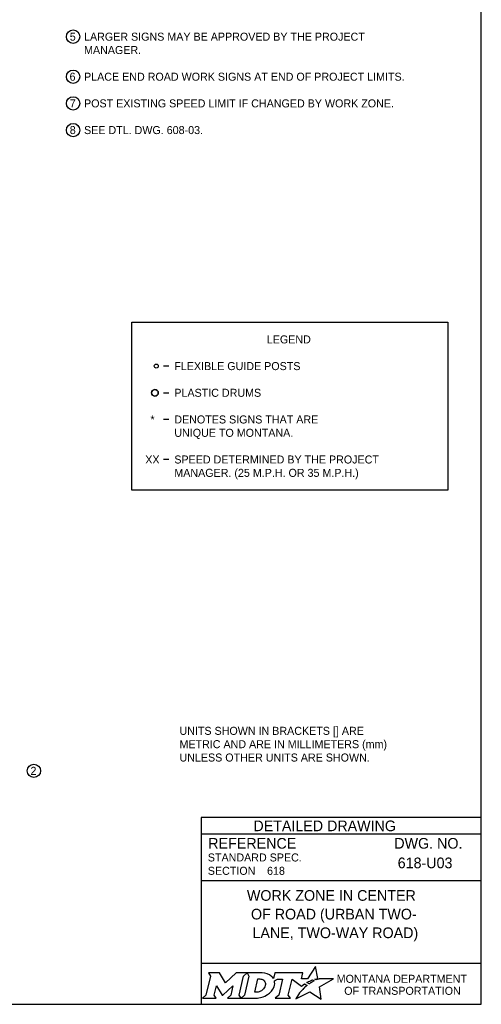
# Model space of a CAD drawing. Extents: x 49991.4 to 50021, y 49987.6 to 50011.4.
# Drawn here: x 50005.15 to 50008.61, y 50000.06 to 50007.44 of the extents above; entities that cross this region are included whole.
import ezdxf

# ---------------------------------------------------------------- set-up
doc = ezdxf.new("R2010")
doc.units = 0
doc.layers.add('Level 1', color=7, linetype='Continuous')
doc.layers.add('Level 2', color=7, linetype='Continuous')

msp = doc.modelspace()

# ---------------------------------------------------------------- linework, layer by layer
at = {"layer": 'Level 1'}
msp.add_lwpolyline([(50008.6146, 50011.2628), (50000.3356, 50011.2628), (50000.3356, 50000.0624), (50008.6146, 50000.0624)], close=True, dxfattribs=at)
for centre, radius in [((50006.1788, 50004.8458), 0.015), ((50006.1688, 50004.6458), 0.025)]:
    msp.add_circle(centre, radius, dxfattribs=at)
for start, end in [(360, 180), (180, 0)]:
    msp.add_arc((50006.1688, 50004.6458), 0.025, start, end, dxfattribs=at)
at = {"layer": 'Level 2'}
for p, q in [((50005.996, 50003.9158), (50005.996, 50005.1758)), ((50006.2738, 50004.8458), (50006.2338, 50004.8458)), ((50006.2338, 50004.6458), (50006.2738, 50004.6458)), ((50006.2738, 50004.4458), (50006.2338, 50004.4458)), ((50006.2738, 50004.1458), (50006.2338, 50004.1458)), ((50008.3627, 50003.9158), (50005.996, 50003.9158)), ((50008.6146, 50001.4624), (50006.5146, 50001.4624)), ((50006.5146, 50001.4624), (50006.5146, 50000.0624)), ((50008.6146, 50001.3374), (50006.5146, 50001.3374)), ((50008.2507, 50001.1223), (50008.2507, 50001.1223)), ((50007.0089, 50001.0629), (50007.0089, 50001.0629)), ((50008.6146, 50000.9874), (50006.5146, 50000.9874)), ((50007.5646, 50000.7383), (50007.5646, 50000.7383)), ((50008.6146, 50000.3693), (50006.5146, 50000.3693))]:
    msp.add_line(p, q, dxfattribs=at)
for points in [[(50005.996, 50005.1758), (50008.3627, 50005.1758), (50008.3627, 50003.9158)], [(50007.3771, 50000.2447), (50007.3668, 50000.2503), (50007.3784, 50000.2531), (50007.39, 50000.2551), (50007.3726, 50000.3452), (50007.3131, 50000.2539), (50007.2658, 50000.2532), (50007.2761, 50000.2973), (50007.0669, 50000.2974), (50007.0568, 50000.2549), (50007.051, 50000.2632)], [(50006.5701, 50000.2974), (50006.5842, 50000.274), (50006.5507, 50000.1307), (50006.525, 50000.1082), (50006.6266, 50000.1082), (50006.6131, 50000.131), (50006.6293, 50000.2011), (50006.673, 50000.1321), (50006.6783, 50000.1321), (50006.7534, 50000.2016), (50006.737, 50000.1305), (50006.7123, 50000.1085), (50006.8139, 50000.1085), (50006.8001, 50000.1318), (50006.8333, 50000.2742)], [(50006.8333, 50000.2742), (50006.8586, 50000.2974), (50006.7762, 50000.2974), (50006.6966, 50000.2244), (50006.6521, 50000.2971), (50006.5701, 50000.2974)], [(50006.9722, 50000.2974), (50006.8586, 50000.2974), (50006.8733, 50000.2745), (50006.8394, 50000.1307), (50006.8139, 50000.1085), (50006.9245, 50000.1085)], [(50006.9962, 50000.2107), (50006.995, 50000.2026), (50006.9918, 50000.1933), (50006.9876, 50000.1851), (50006.982, 50000.1776), (50006.9755, 50000.1707), (50006.9676, 50000.1644), (50006.9593, 50000.1597), (50006.9502, 50000.1558), (50006.9411, 50000.1535), (50006.9319, 50000.1526), (50006.916, 50000.1526), (50006.9396, 50000.2526), (50006.9556, 50000.2526), (50006.9632, 50000.252), (50006.9708, 50000.2501), (50006.9774, 50000.2471), (50006.9835, 50000.2429), (50006.9883, 50000.2379), (50006.992, 50000.2319), (50006.9947, 50000.2257), (50006.9963, 50000.2183), (50006.9963, 50000.2153), (50006.9962, 50000.2107)], [(50007.0636, 50000.2383), (50007.0882, 50000.2514), (50007.1251, 50000.2514), (50007.0965, 50000.1309), (50007.069, 50000.1082), (50007.1852, 50000.1082), (50007.1682, 50000.1311), (50007.1964, 50000.2513), (50007.2677, 50000.1996), (50007.2888, 50000.2147), (50007.3085, 50000.2038)], [(50007.2527, 50000.1479), (50007.2374, 50000.1235), (50007.2327, 50000.116), (50007.2269, 50000.1074), (50007.2246, 50000.1031), (50007.3299, 50000.1562), (50007.4138, 50000.1011), (50007.4007, 50000.1938), (50007.5076, 50000.2522), (50007.4583, 50000.253), (50007.4282, 50000.2534), (50007.4074, 50000.2537), (50007.4006, 50000.2522), (50007.3957, 50000.251), (50007.3873, 50000.2487), (50007.3771, 50000.2447)], [(50007.3267, 50000.2171), (50007.3243, 50000.2154), (50007.306, 50000.225), (50007.3163, 50000.2307), (50007.3204, 50000.2329), (50007.329, 50000.2369), (50007.3347, 50000.2395), (50007.3426, 50000.2425), (50007.3499, 50000.2452), (50007.3617, 50000.2378), (50007.3577, 50000.2357), (50007.3531, 50000.2332), (50007.3489, 50000.231), (50007.3439, 50000.2281), (50007.342, 50000.227), (50007.3393, 50000.2254), (50007.3368, 50000.224), (50007.3345, 50000.2224), (50007.3319, 50000.2206), (50007.3292, 50000.2188), (50007.3267, 50000.2171)], [(50007.2666, 50000.164), (50007.2666, 50000.164)], [(50006.9702, 50000.1158), (50006.9786, 50000.1184), (50006.9916, 50000.1238), (50007.012, 50000.1348)]]:
    msp.add_lwpolyline(points, dxfattribs=at)
for centre in [(50005.5555, 50007.3149), (50005.5555, 50007.0149), (50005.5555, 50006.8149), (50005.5555, 50006.6149), (50005.2612, 50001.8123)]:
    msp.add_circle(centre, 0.0501, dxfattribs=at)
for centre, radius, start, end in [((50006.9953, 50000.219), 0.0709, 339.53292, 15.85821), ((50006.9513, 50000.2363), 0.1183, 300.91025, 339.13831)]:
    msp.add_arc(centre, radius, start, end, dxfattribs=at)
for centre, major_axis, ratio, start_param, end_param in [((50006.9701, 50000.25), (0.0834, -0.0037), 0.568097, 0.61298, 1.570796), ((50007.0257, 50000.2573), (0.0361, -0.0295), 0.469099, 1.225588, 1.570796), ((50007.2597, 50000.1559), (-0.00694, -0.00806), 0.008222, 0, 3.137361), ((50007.2764, 50000.1742), (-0.0098, -0.0102), 0.016458, 3.141593, 6.279097), ((50007.2974, 50000.1941), (-0.0112, -0.0097), 0.021651, 3.157348, 6.283185), ((50006.9248, 50000.2568), (0, 0.1484), 0.987302, 3.139398, 3.456847)]:
    msp.add_ellipse(centre, major_axis=major_axis, ratio=ratio, start_param=start_param, end_param=end_param, dxfattribs=at)

# ---------------------------------------------------------------- texts
for s, height, p in [('5', 0.06, (50005.5303, 50007.2849)), ('LARGER SIGNS MAY BE APPROVED BY THE PROJECT', 0.06, (50005.6372, 50007.2848)), ('MANAGER.', 0.06, (50005.6372, 50007.1848)), ('6', 0.06, (50005.5287, 50006.9849)), ('PLACE END ROAD WORK SIGNS AT END OF PROJECT LIMITS.', 0.06, (50005.6372, 50006.9848)), ('7', 0.06, (50005.5303, 50006.7849)), ('POST EXISTING SPEED LIMIT IF CHANGED BY WORK ZONE.', 0.06, (50005.6372, 50006.7848)), ('8', 0.06, (50005.5303, 50006.5849)), ('SEE DTL. DWG. 608-03.', 0.06, (50005.6372, 50006.5848)), ('LEGEND', 0.06, (50007.0069, 50005.0158)), ('FLEXIBLE GUIDE POSTS', 0.06, (50006.3138, 50004.8158)), ('PLASTIC DRUMS', 0.06, (50006.3138, 50004.6158)), ('*', 0.06, (50006.1352, 50004.4158)), ('DENOTES SIGNS THAT ARE', 0.06, (50006.3138, 50004.4158)), ('UNIQUE TO MONTANA.', 0.06, (50006.3138, 50004.3158)), ('XX', 0.06, (50006.096, 50004.1158)), ('SPEED DETERMINED BY THE PROJECT', 0.06, (50006.3138, 50004.1158)), ('MANAGER. (25 M.P.H. OR 35 M.P.H.)', 0.06, (50006.3138, 50004.0158)), ('2', 0.06, (50005.236, 50001.7823)), ('DETAILED DRAWING', 0.0799, (50006.9063, 50001.3599)), ('REFERENCE', 0.08, (50006.5682, 50001.229)), ('DWG. NO.', 0.08, (50007.9624, 50001.229)), ('STANDARD SPEC.', 0.06, (50006.5649, 50001.133)), ('618-U03', 0.08, (50007.9881, 50001.0823)), ('SECTION', 0.06, (50006.5649, 50001.033)), ('618', 0.06, (50007.0089, 50001.0329)), ('WORK ZONE IN CENTER', 0.08, (50006.8579, 50000.8383)), ('OF ROAD (URBAN TWO-', 0.08, (50006.8882, 50000.6983)), ('LANE, TWO-WAY ROAD)', 0.08, (50006.8996, 50000.5583)), ('MONTANA DEPARTMENT', 0.06, (50007.5308, 50000.2236)), ('OF TRANSPORTATION', 0.06, (50007.587, 50000.1336))]:
    msp.add_text(s, height=height, dxfattribs=at).set_placement(p)
for s, p in [('UNITS SHOWN IN BRACKETS [] ARE ', (50006.3524, 50002.0821)), ('METRIC AND ARE IN MILLIMETERS (mm) ', (50006.3524, 50001.9821)), ('UNLESS OTHER UNITS ARE SHOWN.', (50006.3524, 50001.8821))]:
    msp.add_text(s, height=0.06, rotation=360, dxfattribs=at).set_placement(p)

doc.saveas('drawing.dxf')
